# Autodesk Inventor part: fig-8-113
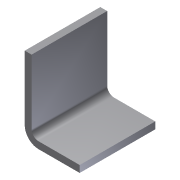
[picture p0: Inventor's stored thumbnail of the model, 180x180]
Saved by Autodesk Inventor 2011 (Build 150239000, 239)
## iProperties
Created: 2009-09
Part Number: fig-8-113
Document SubType Name: Modeling
Designer: Sham
Density: 1 g/cm^3
Author: Sham
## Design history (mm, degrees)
sketch "Sketch1"
  geometry: L1 (-33.976, 22)-(0, 22); L2 (0, 22)-(0, 0); L3 (0, 0)-(-33.976, 0); L4 (-33.976, 0)-(-33.976, 22)
  constraints: 8 end point, 2 parallel, 1 horizontal, 1 perpendicular
extrude "Extrusion1" new body sketch "Sketch1" distance "d0" = 2; taper "d1" = 0 deg
sketch "Sketch2"
  geometry: L1 (-12, 22)-(-12, 0)
  constraints: 2 end point
feature "Bend Part1" sketch "Sketch2" dims "d5" = 90 deg, "d6" = 2
body "Solid1"
